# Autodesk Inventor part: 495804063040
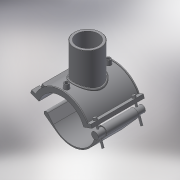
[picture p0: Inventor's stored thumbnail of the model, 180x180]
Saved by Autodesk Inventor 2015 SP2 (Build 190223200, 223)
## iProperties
Created: 2017-07
Part Number: 495804063040
Material: Generic
Description: PLASSON BRANCH SADDLE 63-40
Document SubType Name: Modeling
Designer: KIM
Density: 1 g/cm^3
Appearance: Default
Author: KIM
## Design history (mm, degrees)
derived "495804.ipt"
feature "Solid1::495804.ipt"
feature "Solid2::495804.ipt"
tag "TaggingFeature1"
body "Solid1"
body "Solid2"
other parameters: "d0" = 63, "d3" = 15.75, "d4" = 118, "d5" = 0, "d6" = 0.1, "d8" = 0, "d19" = 6, "d20" = 6, "d21" = 70.8, "d23" = 0, "d24" = 35.4, "d26" = 0, "d27" = 3, "d28" = 3, "d29" = 3, "d30" = 21, "d31" = 6, "d32" = 0, "d33" = 0, "d34" = 0.6, "d40" = 45.24, "d41" = 44, "d43" = 0, "d45" = 0, "d47" = 121.5, "d50" = 0, "d70" = 15, "d72" = 0, "d73" = 6, "d75" = 5, "d76" = 0, "d77" = 3.15, "d78" = 61.5, "d79" = 15, "d80" = 47.2, "d82" = 5 deg, "d84" = 4, "d85" = 14, "d86" = 0, "d87" = 3, "d88" = 0, "d89" = 1, "d90" = 1, "d91" = 94.4, "d92" = 0, "d93" = 0.5, "d94" = 33.15789, "d96" = 88.74, "d97" = 2.36, "d98" = 0, "d102" = 1.2, "d103" = 32, "d105" = 0, "d109" = -26, "d117" = 0.4, "d120" = 140 deg, "d121" = 24.228, "d122" = 20 deg, "d123" = 174, "d124" = 52.2, "d126" = 0, "d143" = 66.15, "d150" = 11.34, "d159" = 4.8, "d161" = 1.575, "d162" = 70.8, "d163" = 0, "d167" = 12.6, "d168" = 39.54545, "d173" = 1, "d175" = 31.5, "d176" = 20 deg, "d177" = 4.41, "d178" = 24, "d180" = 0, "d185" = 38.35, "d186" = 38.35, "d187" = 43.5, "d188" = 7.2, "d189" = 4.41, "d190" = 0, "d191" = 65.25, "d200" = 12, "d202" = 0, "d216" = 106.2, "d217" = 0, "d221" = 43.66, "d222" = 4.41, "d223" = 2.646, "d224" = 31.5, "d225" = 2.646, "d227" = 9.072, "d230" = 39.06, "d236" = 20 deg, "d237" = 50.5, "d238" = 20 deg, "d239" = 4.41, "d_" = 63, "H_" = 78, "L_" = 118, "d_t" = 6, "H_1" = 66, "d1" = 87, "d148" = 1.575, "d160" = 1.575
